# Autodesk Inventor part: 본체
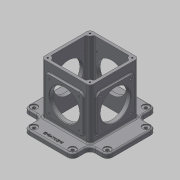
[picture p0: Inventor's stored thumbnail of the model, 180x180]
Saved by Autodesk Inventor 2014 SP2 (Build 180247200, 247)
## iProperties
Created: 2018-09
Part Number: 본체
Material: 일반
Document SubType Name: Modeling
Designer: mduedu
Density: 1 g/cm^3
Appearance: 기본값
Author: mduedu
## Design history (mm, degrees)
sketch "스케치1"
  geometry: L1 (90, 52.5)-(-90, 52.5); L2 (-90, 52.5)-(-90, -52.5); L3 (-90, -52.5)-(90, -52.5); L4 (90, -52.5)-(90, 52.5); L5 (90, 52.5)-(-90, -52.5); L6 (-90, 52.5)-(90, -52.5); L7 (-52.5, -90)-(52.5, -90); L8 (52.5, -90)-(52.5, 90); L9 (52.5, 90)-(-52.5, 90); L10 (-52.5, 90)-(-52.5, -90); L11 (-52.5, -90)-(52.5, 90); L12 (52.5, -90)-(-52.5, 90); 1 further point
  constraints: 24 end point, 4 midpoint, 4 parallel, 2 horizontal, 2 perpendicular
  dimensions: "d0" = 180 distance of L3.end L2.end; "d1" = 105 distance of L2.end L1.end; "d105" = 105 distance of L9.end L8.end; "d106" = 180 distance of L8.end L7.end
extrude "돌출1" new body sketch "스케치1" distance "d2" = 10; taper "d3" = 0 deg
fillet "모깎기16" dims "d107" = 11
sketch "스케치2"
  geometry: L1 (-52.5, -52.5)-(52.5, -52.5); L2 (52.5, -52.5)-(52.5, 52.5); L3 (52.5, 52.5)-(-52.5, 52.5); L4 (-52.5, 52.5)-(-52.5, -52.5); L5 (-52.5, -52.5)-(52.5, 52.5); L6 (52.5, -52.5)-(-52.5, 52.5); 1 further point
  constraints: 12 end point, 2 midpoint, 2 parallel, 1 horizontal, 1 perpendicular
  dimensions: "d4" = 105 distance of L3.end L2.end; "d5" = 105 distance of L2.end L1.end
extrude "돌출2" join sketch "스케치2" distance "d6" = 110; taper "d7" = 0 deg
sketch "스케치14"
  geometry: L1 (-52.5, 52.5)-(52.5, 52.5) reference; L2 (52.5, 52.5)-(52.5, -52.5) reference; L3 (52.5, -52.5)-(-52.5, -52.5) reference; L4 (-52.5, -52.5)-(-52.5, 52.5) reference; L5 (46.5, 46.5)-(-46.5, 46.5); L6 (-46.5, 46.5)-(-46.5, -46.5); L7 (-46.5, -46.5)-(46.5, -46.5); L8 (46.5, -46.5)-(46.5, 46.5); 1 further point
  constraints: 8 end point, 3 other
  dimensions: "d85" = 6 distance between parallel lines of L5 L1
extrude "돌출10" cut sketch "스케치14" stored distance "d86" = 10; taper "d87" = 0 deg
fillet "모깎기1" dims "d12" = 7
sketch "스케치15"
  geometry: A1 r 7 centre (-45.5, 45.5) between (-45.5, 52.5) and (-52.5, 45.5) reference; A2 r 7 centre (45.5, 45.5) between (52.5, 45.5) and (45.5, 52.5) reference; A3 r 7 centre (45.5, -45.5) between (45.5, -52.5) and (52.5, -45.5) reference; A4 r 7 centre (-45.5, -45.5) between (-52.5, -45.5) and (-45.5, -52.5) reference; 5 further points
  constraints: 4 coincident, 4 vertical alignment, 8 other
extrude "돌출11" join sketch "스케치15" stored distance "d88" = 10; taper "d89" = 0 deg
fillet "모깎기15" dims "d90" = 3
sketch "스케치6"
  geometry: L1 (50, 20)-(130, 20); L2 (130, 20)-(130, 100); L3 (130, 100)-(50, 100); L4 (50, 100)-(50, 20); L5 (50, 20)-(130, 100); L6 (130, 20)-(50, 100); L7 (0, 0)-(180, 0) reference; 4 further points
  constraints: 12 end point, 4 midpoint, 2 parallel, 1 horizontal, 1 perpendicular, 1 vertical alignment
  dimensions: "d25" = 80 distance of L3.end L2.end; "d26" = 80 distance of L2.end L1.end; "d27" = 60 distance of point (90, 0) point (90, 60)
extrude "돌출6" join sketch "스케치6" distance "d28" = 3; taper "d29" = 0 deg
fillet "모깎기7" dims "d30" = 8
sketch "스케치7"
  geometry: C1 r 32.5 at (90, 60); 1 further point
  constraints: 1 centre point, 1 vertical alignment
  dimensions: "d32" = 65 diameter of C1; "d33" = 60 distance of C1.centre point (90, 0)
extrude "돌출7" cut sketch "스케치7" stored distance "d34" = 3; taper "d35" = 0 deg
fillet "모깎기9" dims "d36" = 3
sketch "스케치8"
  geometry: L1 (5.5, 10)-(85.5, 10); L2 (85.5, 10)-(85.5, 90); L3 (85.5, 90)-(5.5, 90); L4 (5.5, 90)-(5.5, 10); L5 (5.5, 10)-(85.5, 90); L6 (85.5, 10)-(5.5, 90); L7 (-7, -10)-(98, -10) reference; C1 r 32.5 at (45.5, 50); 4 further points
  constraints: 12 end point, 4 midpoint, 2 parallel, 1 centre point, 1 coincident, 1 horizontal, 1 perpendicular, 1 vertical alignment
  dimensions: "d37" = 80 distance of L3.end L2.end; "d38" = 80 distance of L2.end L1.end; "d39" = 60 distance from line of point (45.5, 50) L7; "d40" = 65 diameter of C1
extrude "돌출8" join sketch "스케치8" distance "d41" = 3; taper "d42" = 0 deg
fillet "모깎기10" dims "d43" = 8
extrude "돌출9" cut sketch "스케치8" stored distance "d44" = 3; taper "d45" = 0 deg
fillet "모깎기11" dims "d46" = 3
sketch "스케치9"
  geometry: L1 (50, 92)-(50, 28) reference; L2 (58, 20)-(122, 20) reference; L3 (130, 28)-(130, 92) reference; L4 (122, 100)-(58, 100) reference; C1 r 32.5 at (90, 60) reference; A1 r 8 centre (58, 92) between (58, 100) and (50, 92) reference; A2 r 8 centre (58, 28) between (50, 28) and (58, 20) reference; A3 r 8 centre (122, 28) between (122, 20) and (130, 28) reference; A4 r 8 centre (122, 92) between (130, 92) and (122, 100) reference; 5 further points
  constraints: 4 coincident
hole "구멍1" sketch "스케치9" at (58, 92), (122, 92), (122, 28), (58, 28) diameter "d47" = 3.242; stored, may be unused: countersink angle "d51" = 90 deg, drill point angle "d53" = 118 deg; dims "d48" = 6, "d49" = 4, "d50" = 2, "d52" = 9
sketch "스케치10"
  geometry: L1 (13.5, 10)-(77.5, 10) reference; L2 (85.5, 18)-(85.5, 82) reference; L3 (77.5, 90)-(13.5, 90) reference; L4 (5.5, 82)-(5.5, 18) reference; C1 r 32.5 at (45.5, 50) reference; A1 r 8 centre (13.5, 18) between (5.5, 18) and (13.5, 10) reference; A2 r 8 centre (77.5, 18) between (77.5, 10) and (85.5, 18) reference; A3 r 8 centre (77.5, 82) between (85.5, 82) and (77.5, 90) reference; A4 r 8 centre (13.5, 82) between (13.5, 90) and (5.5, 82) reference; 5 further points
  constraints: 4 coincident
hole "구멍2" sketch "스케치10" at (13.5, 82), (77.5, 82), (77.5, 18), (13.5, 18) diameter "d54" = 3.242; stored, may be unused: countersink angle "d58" = 90 deg, drill point angle "d60" = 118 deg; dims "d55" = 6, "d56" = 4, "d57" = 2, "d59" = 9
fillet "모깎기12" dims "d68" = 11
sketch "스케치16"
  geometry: A1 r 11 centre (-79, 41.5) between (-79, 52.5) and (-90, 41.5) reference; A2 r 11 centre (-79, -41.5) between (-90, -41.5) and (-79, -52.5) reference; A3 r 11 centre (79, 41.5) between (90, 41.5) and (79, 52.5) reference; A4 r 11 centre (79, -41.5) between (79, -52.5) and (90, -41.5) reference; A5 r 11 centre (-41.5, 79) between (-41.5, 90) and (-52.5, 79) reference; A6 r 11 centre (41.5, 79) between (52.5, 79) and (41.5, 90) reference; A7 r 11 centre (41.5, -79) between (41.5, -90) and (52.5, -79) reference; A8 r 11 centre (-41.5, -79) between (-52.5, -79) and (-41.5, -90) reference; 9 further points
  constraints: 8 coincident
hole "구멍5" sketch "스케치16" at (-79, 41.5), (79, 41.5), (79, -41.5), (-79, -41.5), (41.5, 79), (-41.5, 79), (-41.5, -79), (41.5, -79) diameter "d91" = 6.6; stored, may be unused: countersink angle "d95" = 90 deg, drill point angle "d97" = 118 deg; dims "d92" = 6, "d93" = 15, "d94" = 2, "d96" = 8
fillet "모깎기13" dims "d77" = 3
chamfer "모따기1" distance "d79" = 1; stored, may be unused: second distance "d80" = 2, angle "d81" = 45 deg
sketch "스케치17"
  geometry: A1 r 7 centre (-45.5, 45.5) between (-45.5, 52.5) and (-52.5, 45.5) reference; A2 r 7 centre (-45.5, -45.5) between (-52.5, -45.5) and (-45.5, -52.5) reference; A3 r 7 centre (45.5, -45.5) between (45.5, -52.5) and (52.5, -45.5) reference; A4 r 7 centre (45.5, 45.5) between (52.5, 45.5) and (45.5, 52.5) reference; 5 further points
  constraints: 4 coincident
hole "구멍6" sketch "스케치17" at (-45.5, 45.5), (45.5, 45.5), (45.5, -45.5), (-45.5, -45.5) diameter "d98" = 3.242; stored, may be unused: countersink angle "d102" = 90 deg, drill point angle "d104" = 118 deg; dims "d99" = 8, "d100" = 15, "d101" = 2, "d103" = 10
sketch "스케치13"
  geometry: L1 (90, -41.5)-(90, 41.5) reference; 2 further points
  constraints: 1 horizontal alignment, 1 other
  dimensions: "d82" = 11 distance from line of point (79, 0) L1
feature "엠보싱1" sketch "스케치13" dims "d0" = 180, "d1" = 105, "d83" = 0.5, "d84" = 0
node "솔리드1"
mirror "대칭1"
mirror "대칭4"
mirror "대칭2"
mirror "대칭5"
node "투영된 루프2"
node "투영된 루프3"
node "투영된 루프6"
